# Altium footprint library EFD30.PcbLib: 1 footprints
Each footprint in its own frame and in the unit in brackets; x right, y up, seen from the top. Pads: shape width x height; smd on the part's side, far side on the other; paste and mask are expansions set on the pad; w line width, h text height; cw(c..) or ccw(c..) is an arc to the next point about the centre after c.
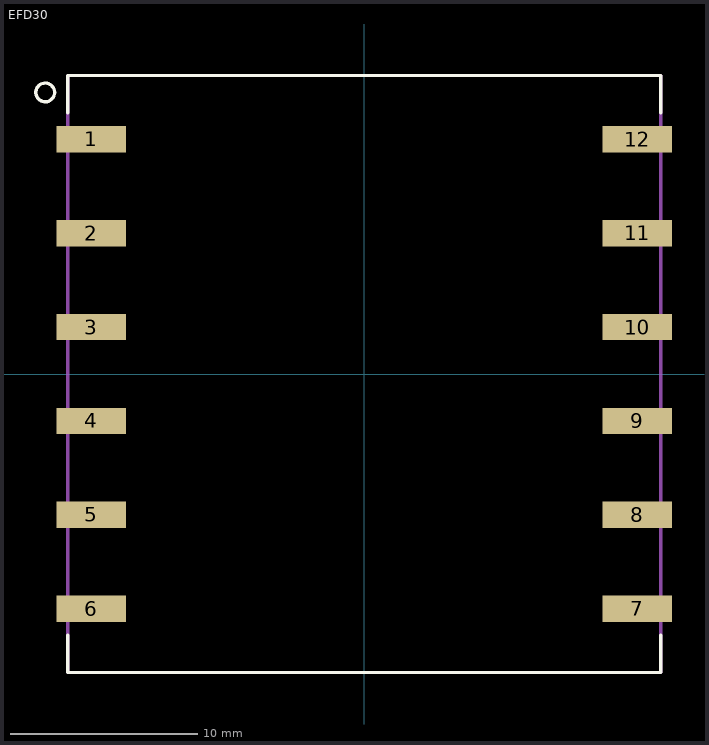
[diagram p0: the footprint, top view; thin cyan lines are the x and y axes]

## EFD30 [mm] "Recommended land pattern for Pulse EFD transformer"
height 14.8
pads (12):
  rect 3.7x1.4 smd: 1(-14.55,12.5) 2(-14.55,7.5) 3(-14.55,2.5) 4(-14.55,-2.5) 5(-14.55,-7.5) 6(-14.55,-12.5) 7(14.55,-12.5) 8(14.55,-7.5) 9(14.55,-2.5) 10(14.55,2.5) 11(14.55,7.5) 12(14.55,12.5)
Top Overlay:
  circle w0.178: c-17,15 r0.5
  lines w0.178: -15.8,-13.9 -15.8,-15.9 0,-15.9 15.8,-15.9 15.8,-13.9 ; -15.8,13.9 -15.8,15.9 0,15.9 15.8,15.9 15.8,13.9
M5 Assembly Top:
  text ".designator" at -1.219,-0.635 h1.52
M13 Component Bodies Top:
  lines w0.178: -15.8,-15.9 15.8,-15.9 15.8,15.9 -15.8,15.9 -15.8,-15.9
3D body: height 14.8, standoff 0, extent -15.8,-15.9 15.8,15.9
3D body: height 8.89, standoff 8.89, extent -12.255,11.745 -10.745,13.255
